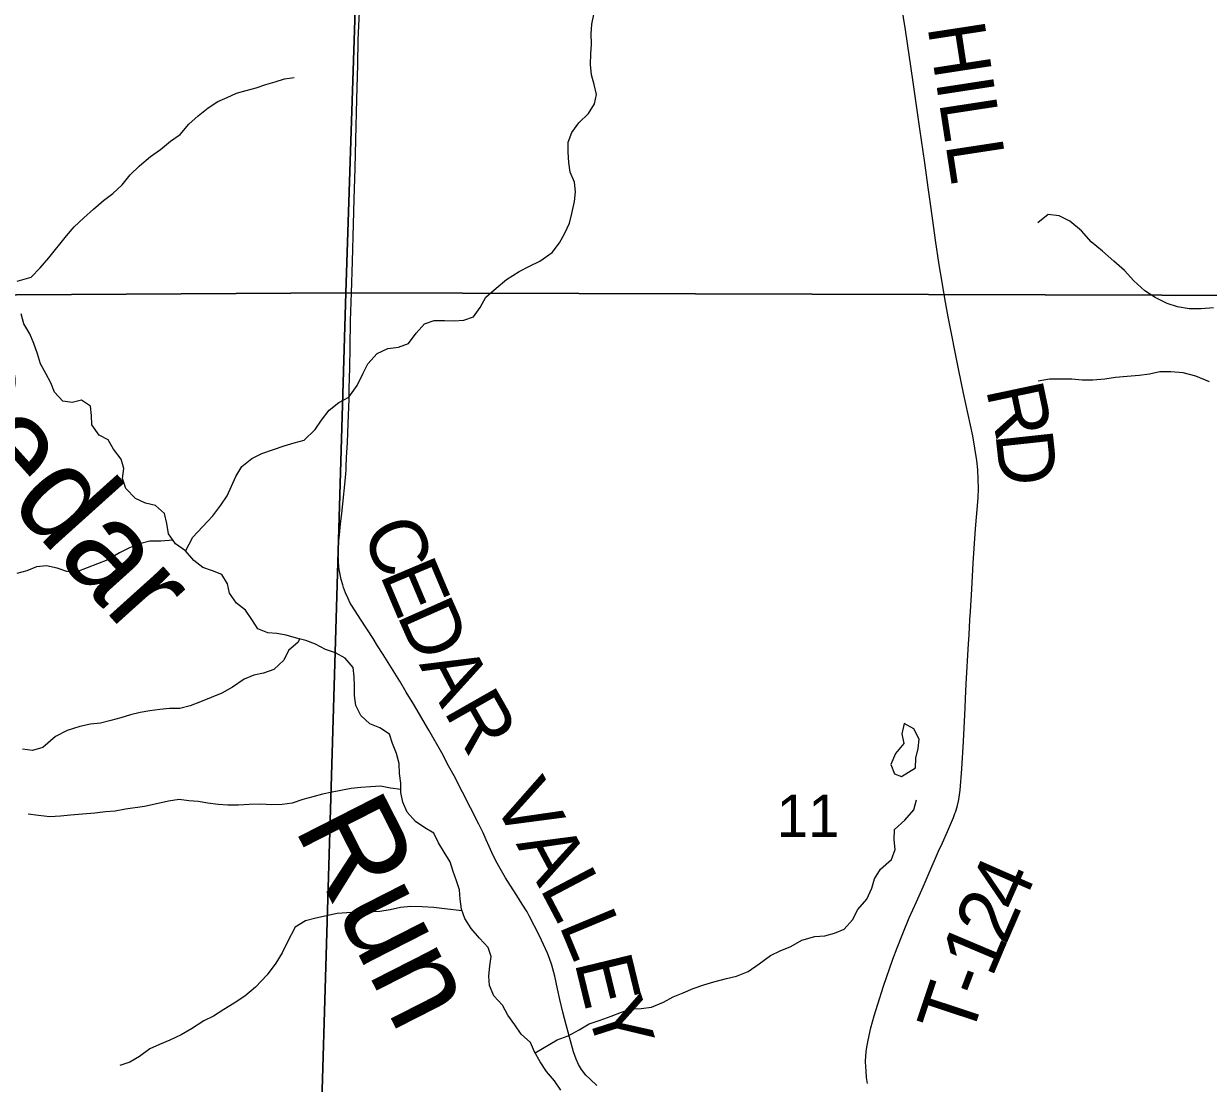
# Model space of a CAD drawing. Extents: x 1985906 to 2360102, y 891258 to 1222054.
# Drawn here: x 2095891 to 2102102, y 1047944 to 1053500 of the extents above; entities that cross this region are included whole.
import ezdxf

# ---------------------------------------------------------------- set-up
doc = ezdxf.new("R2010")
doc.units = 0
for name, color, linetype in [('GM_X_County_Road', 7, 'Continuous'), ('GM_X_County_Road_Text', 7, 'Continuous'), ('GM_X_Minor_Lake', 7, 'Continuous'), ('GM_X_Minor_River', 7, 'Continuous'), ('GM_X_Minor_River_Text', 7, 'Continuous'), ('GM_X_Section', 7, 'Continuous'), ('GM_X_Section_Text', 7, 'Continuous'), ('GM_X_Township_Road', 7, 'Continuous'), ('GM_X_Township_Road_Text', 7, 'Continuous')]:
    doc.layers.add(name, color=color, linetype=linetype)

msp = doc.modelspace()

# ---------------------------------------------------------------- linework, layer by layer
at = {"layer": 'GM_X_County_Road'}
msp.add_lwpolyline([(2098896.2, 1047932.2), (2098860, 1047965.5), (2098837.4, 1047987.2), (2098814.8, 1048015.9), (2098799.2, 1048042.8), (2098787, 1048069.7), (2098774.1, 1048109.6), (2098762.7, 1048147), (2098734.1, 1048250.3), (2098717.6, 1048316.3), (2098702, 1048382.3), (2098689.9, 1048439.6), (2098676, 1048504.8), (2098659.5, 1048563), (2098645.7, 1048603.5), (2098636.8, 1048626.7), (2098627.4, 1048648.9), (2098595.3, 1048716.7), (2098541.4, 1048821.3), (2098529.6, 1048842.5), (2098504.3, 1048882.6), (2098475.9, 1048927.7), (2098441.6, 1048983.4), (2098416.4, 1049021.5), (2098388.7, 1049069.3), (2098367, 1049110.9), (2098345.3, 1049154.7), (2098331.6, 1049185.2), (2098316.2, 1049219.7), (2098299.2, 1049257.6), (2098277.6, 1049302.9), (2098147.5, 1049555.2), (2098118.5, 1049608.9), (2098082.3, 1049676.3), (2098014.5, 1049796.1), (2097935.5, 1049930.7), (2097896.5, 1049994.1), (2097862.2, 1050051.5), (2097774.8, 1050192), (2097746, 1050238.3), (2097722.9, 1050275.5), (2097656.9, 1050377.1), (2097612.9, 1050445), (2097603.2, 1050462.2), (2097590, 1050489.1), (2097577.9, 1050516.1), (2097567.3, 1050542.9), (2097563.3, 1050556.9), (2097555.3, 1050584.7), (2097545.1, 1050638.7), (2097542.9, 1050650.8), (2097540.6, 1050681.9), (2097539.7, 1050718.4), (2097541.5, 1050772.2), (2097545.8, 1050820), (2097551.9, 1050877.3), (2097558.9, 1050931.1), (2097564, 1050981.5), (2097576.1, 1051100.4), (2097579.1, 1051138.7), (2097580.9, 1051161.3), (2097581.5, 1051177.1), (2097583.5, 1051224.7), (2097587.6, 1051304), (2097590.3, 1051352.3), (2097592, 1051403.5), (2097596.3, 1051532.9), (2097597.8, 1051586.7), (2097600.8, 1051695.4), (2097602.5, 1051803.8), (2097604.7, 1051940.9), (2097609.7, 1052088.2), (2097614, 1052252.1), (2097620.1, 1052448.6), (2097623.3, 1052579.6), (2097628, 1052743.1), (2097631.6, 1052890.5), (2097637.2, 1053103.4), (2097642, 1053283.6), (2097644.9, 1053414.8), (2097650.8, 1053561.8)], dxfattribs=at)
at = {"layer": 'GM_X_Minor_Lake'}
msp.add_line((2100457.3, 1049565.6), (2100493.3, 1049553), dxfattribs=at)
msp.add_lwpolyline([(2100493.3, 1049553), (2100566.2, 1049598.2), (2100569, 1049648.4), (2100579.7, 1049698.5), (2100586.5, 1049748.6), (2100557.1, 1049803.2), (2100507.3, 1049830), (2100494.5, 1049775.9), (2100505.8, 1049725.6), (2100460.9, 1049673.9), (2100438, 1049616), (2100457.3, 1049565.6)], dxfattribs=at)
at = {"layer": 'GM_X_Minor_River'}
for points in [[(2096739.7, 1050734.8), (2096777.9, 1050807.7), (2096828.9, 1050861.2), (2096881.9, 1050918.7), (2096924.9, 1050974.4), (2096957.8, 1051024.1), (2096980.6, 1051074), (2097003.4, 1051125.9), (2097034.3, 1051177.8), (2097087.1, 1051219.2), (2097139.7, 1051246.6), (2097200.2, 1051267.9), (2097256.7, 1051287.2), (2097309.2, 1051302.6), (2097361.6, 1051316), (2097418.6, 1051371.4), (2097451.5, 1051421.2), (2097492.4, 1051472.8), (2097543.2, 1051514.3), (2097595.8, 1051541.8), (2097638.8, 1051603.4), (2097669.9, 1051667.3), (2097694.7, 1051717.1), (2097743.7, 1051770.7), (2097800.3, 1051796.1), (2097856.6, 1051803.3), (2097909.1, 1051822.7), (2097948, 1051876.4), (2097992.9, 1051926), (2098043.4, 1051943.4), (2098097.6, 1051942.7), (2098147.8, 1051942), (2098198, 1051945.4), (2098248.5, 1051962.8), (2098283.3, 1052012.5), (2098314.2, 1052066.3), (2098367.1, 1052113.8), (2098422, 1052159.2), (2098488.9, 1052200.5), (2098543.5, 1052227.9), (2098596.1, 1052255.3), (2098661, 1052300.6), (2098699.9, 1052350.3), (2098728.8, 1052402.2), (2098751.6, 1052454.1), (2098764.4, 1052504.1), (2098779.3, 1052568.2), (2098784.1, 1052618.3), (2098778.8, 1052668.6), (2098755.4, 1052721.1), (2098748.1, 1052771.4), (2098744.9, 1052825.7), (2098745.6, 1052877.9), (2098764.5, 1052929.8), (2098801.3, 1052979.5), (2098852.2, 1053029.1), (2098883.1, 1053078.9), (2098893.8, 1053128.9), (2098882.5, 1053181.3), (2098867.2, 1053231.7), (2098861.9, 1053286), (2098864.8, 1053342.2), (2098867.5, 1053392.3), (2098866.3, 1053446.6), (2098869, 1053496.8), (2098879.8, 1053548.8)], [(2095856.5, 1052149.1), (2095929.9, 1052170.5), (2095976.8, 1052220.1), (2096021.7, 1052271.7), (2096115.8, 1052386.9), (2096154.6, 1052434.6), (2096205.5, 1052482.1), (2096256.3, 1052527.6), (2096309.2, 1052573.1), (2096357.9, 1052608.6), (2096406.8, 1052654.1), (2096449.7, 1052707.8), (2096498.6, 1052755.3), (2096555.5, 1052802.8), (2096608.3, 1052840.2), (2096661.1, 1052883.7), (2096711.8, 1052919.1), (2096756.8, 1052972.8), (2096805.6, 1053016.3), (2096858.4, 1053057.8), (2096909.1, 1053091.2), (2096957.6, 1053112.7), (2097006.1, 1053136.1), (2097056.5, 1053149.5), (2097108.9, 1053162.8), (2097159.4, 1053180.2), (2097209.8, 1053195.6), (2097258.2, 1053211.1), (2097308.6, 1053218.4)], [(2102129.2, 1052009.2), (2102064.8, 1052004), (2102000.6, 1052004.9), (2101940.5, 1052015.8), (2101886.5, 1052032.5), (2101822.7, 1052063.5), (2101768.9, 1052098.4), (2101711.5, 1052151.4), (2101662.1, 1052206.2), (2101606.5, 1052255.2), (2101547, 1052306.2), (2101487.5, 1052355.2), (2101436.1, 1052414.1), (2101376.6, 1052465.1), (2101320.7, 1052492), (2101262.6, 1052498.8), (2101207.7, 1052455.3)], [(2095979.6, 1051716), (2095962.3, 1051768.4), (2095943, 1051822.9), (2095923.6, 1051873.4), (2095892.2, 1051926), (2095876.9, 1051978.4)], [(2098706.4, 1047908.1), (2098673, 1047956.8), (2098631.5, 1048005.5), (2098598.1, 1048056.2), (2098568.7, 1048108.8), (2098547.3, 1048157.3), (2098499.8, 1048202.1), (2098466.3, 1048250.7), (2098428.9, 1048301.4), (2098401.5, 1048354), (2098356, 1048402.8), (2098332.7, 1048457.4), (2098329.4, 1048505.6), (2098334.2, 1048559.8), (2098340.9, 1048607.9), (2098325.5, 1048656.3), (2098280.1, 1048705.1), (2098236.6, 1048755.9), (2098203.2, 1048808.5), (2098185.8, 1048856.9), (2098178.6, 1048909.3), (2098175.2, 1048957.5), (2098159.9, 1049005.9), (2098142.5, 1049054.3), (2098127.1, 1049104.7), (2098095.7, 1049155.4), (2098066.3, 1049204), (2098040.9, 1049254.5), (2097993.1, 1049283.3), (2097945.4, 1049316), (2097901.9, 1049364.8), (2097878.6, 1049417.3), (2097867.3, 1049467.7), (2097868, 1049517.9), (2097860.7, 1049568.2), (2097859.4, 1049620.4), (2097846.1, 1049672.8), (2097824.8, 1049725.3), (2097809.4, 1049773.7), (2097757.7, 1049808.5), (2097705.8, 1049829.3), (2097658.2, 1049872.1), (2097632.8, 1049924.7), (2097625.5, 1049977), (2097624.3, 1050027.2), (2097622.9, 1050075.4), (2097617.6, 1050123.7), (2097576.1, 1050172.4), (2097526.3, 1050201.2), (2097472.4, 1050218), (2097420.6, 1050246.8), (2097370.6, 1050265.6), (2097320.6, 1050278.3), (2097266.6, 1050293.1), (2097218.5, 1050301.7), (2097170.4, 1050306.4), (2097118.5, 1050327.2), (2097087, 1050375.8), (2097053.6, 1050424.4), (2097005.9, 1050461.2), (2096970.5, 1050513.9), (2096959.2, 1050562.2), (2096929.7, 1050610.8), (2096879.8, 1050631.6), (2096829.9, 1050648.3), (2096782.2, 1050685.1), (2096738.7, 1050735.9), (2096687, 1050772.7), (2096649.6, 1050825.4), (2096640.4, 1050879.8), (2096629.1, 1050932.2), (2096581.5, 1050972.9), (2096529.4, 1050985.7), (2096477.6, 1051010.5), (2096426.1, 1051063.4), (2096408.8, 1051115.8), (2096415.6, 1051168), (2096402.2, 1051216.3), (2096360.8, 1051269.1), (2096333.4, 1051317.7), (2096285.5, 1051342.4), (2096248.2, 1051397.1), (2096246.8, 1051445.3), (2096241.5, 1051493.6), (2096193.8, 1051526.4), (2096145.4, 1051513), (2096095.3, 1051519.7), (2096051.8, 1051568.4), (2096032.4, 1051616.9), (2096007, 1051665.4), (2095979.6, 1051716)], [(2102107.5, 1051621.9), (2102035.6, 1051651), (2101969.6, 1051669.9), (2101905.4, 1051674.8), (2101847.2, 1051673.6), (2101792.8, 1051662.3), (2101738.5, 1051655), (2101676.1, 1051649.8), (2101615.8, 1051644.6), (2101559.5, 1051635.3), (2101497.1, 1051630.1), (2101440.9, 1051630.8), (2101386.7, 1051635.6), (2101322.5, 1051636.4), (2101268.3, 1051635.2), (2101209.9, 1051625.9)], [(2096673.9, 1050791.3), (2096608.9, 1050785.8), (2096552.7, 1050786.6), (2096498.3, 1050773.2), (2096445.8, 1050751.9), (2096393.1, 1050724.4), (2096332.4, 1050689.1), (2096168.8, 1050625), (2096116.6, 1050627.7), (2096066.6, 1050644.5), (2096010.6, 1050657.3), (2095958.3, 1050651.9), (2095907.8, 1050630.5), (2095855.4, 1050617.2)], [(2097337.5, 1050274), (2097330.3, 1050256.1), (2097279.5, 1050212.6), (2097254.7, 1050162.7), (2097201.7, 1050113.2), (2097147.2, 1050093.8), (2097096.9, 1050084.5), (2097046.4, 1050063.1), (2096985.5, 1050021.7), (2096928.9, 1049990.3), (2096874.3, 1049967), (2096817.7, 1049943.6), (2096763.2, 1049922.3), (2096708.8, 1049908.9), (2096654.6, 1049909.6), (2096604.3, 1049904.3), (2096552, 1049897), (2096501.6, 1049887.6), (2096451.3, 1049876.2), (2096400.8, 1049860.8), (2096348.4, 1049845.5), (2096294, 1049832.1), (2096241.7, 1049826.8), (2096185.3, 1049815.5), (2096118.7, 1049794.3), (2096058, 1049763), (2095990.9, 1049703.7), (2095936.4, 1049688.3), (2095884.3, 1049695)], [(2097867.5, 1049483.8), (2097813.4, 1049490.5), (2097761.3, 1049501.2), (2097709, 1049497.9), (2097658.8, 1049494.6), (2097608.5, 1049489.2), (2097507.8, 1049470.5), (2097457.4, 1049459.1), (2097407, 1049445.7), (2097354.6, 1049432.4), (2097298.1, 1049413.1), (2097245.8, 1049405.7), (2097191.6, 1049404.4), (2097131.4, 1049407.2), (2097073.1, 1049406), (2097016.8, 1049402.8), (2096960.6, 1049401.5), (2096910.4, 1049406.2), (2096856.3, 1049412.9), (2096806.2, 1049421.6), (2096756.1, 1049424.3), (2096706, 1049431), (2096649.6, 1049423.7), (2096595.2, 1049410.4), (2096524.7, 1049395.3), (2096424.1, 1049380.6), (2096369.7, 1049371.2), (2096319.5, 1049367.9), (2096263.1, 1049360.6), (2096198.8, 1049355.5), (2096136.4, 1049350.3), (2096084.2, 1049344.9), (2096027.9, 1049341.7), (2095967.7, 1049348.5), (2095913.6, 1049355.3)], [(2098571.9, 1048103.1), (2098688.1, 1048171.5), (2098744.6, 1048192.8), (2098803.3, 1048224.1), (2098856, 1048255.6), (2098912.5, 1048274.9), (2098971.1, 1048296.2), (2099025.6, 1048317.6), (2099078.1, 1048334.9), (2099128.3, 1048336.3), (2099182.6, 1048343.6), (2099245.2, 1048368.8), (2099295.8, 1048396.3), (2099348.3, 1048417.7), (2099400.9, 1048441.1), (2099457.4, 1048460.4), (2099509.8, 1048475.8), (2099576.4, 1048492.9), (2099628.8, 1048506.3), (2099689.3, 1048529.6), (2099746.2, 1048571), (2099807, 1048614.3), (2099857.6, 1048637.8), (2099912.1, 1048661.1), (2099970.9, 1048694.5), (2100039.4, 1048713.6), (2100091.7, 1048717), (2100142.1, 1048730.4), (2100192.6, 1048751.8), (2100235.5, 1048801.4), (2100264.4, 1048855.2), (2100311.3, 1048908.8), (2100338.3, 1048966.7), (2100351, 1049016.7), (2100383.9, 1049066.5), (2100440.9, 1049117.9), (2100459.7, 1049169.9), (2100454.4, 1049220.2), (2100457.2, 1049274.4), (2100510.1, 1049323.9), (2100557, 1049377.4), (2100571.9, 1049429.5)], [(2098189.2, 1048847.4), (2098097.5, 1048858.1), (2098041.4, 1048864.9), (2097979.2, 1048869.8), (2097920.9, 1048870.5), (2097866.6, 1048865.2), (2097812.3, 1048853.9), (2097757.9, 1048844.6), (2097693.6, 1048841.4), (2097639.3, 1048840.2), (2097585.1, 1048836.9), (2097534.8, 1048833.5), (2097478.4, 1048822.2), (2097422, 1048808.9), (2097367.6, 1048795.6), (2097314.9, 1048762.2), (2097273.6, 1048686.4), (2097246.7, 1048628.5), (2097211.8, 1048572.8), (2097166.7, 1048513.1), (2097105.5, 1048447.7), (2097050.6, 1048400.2), (2096993.9, 1048364.8), (2096939.2, 1048331.4), (2096886.5, 1048296), (2096835.9, 1048270.6), (2096771, 1048229.3), (2096716.4, 1048197.9), (2096657.7, 1048170.5), (2096603.2, 1048147.2), (2096552.6, 1048123.7), (2096497.8, 1048084.3), (2096447.2, 1048054.9), (2096394.7, 1048037.5)]]:
    msp.add_lwpolyline(points, dxfattribs=at)
at = {"layer": 'GM_X_Section'}
for points in [[(2097994, 1057075.2), (2103253.1, 1057114.6), (2103079.3, 1052072.7), (2097579.8, 1052088.1), (2097743.8, 1057069.9)], [(2092680.8, 1057037.4), (2097743.8, 1057069.9), (2097579.8, 1052088.1), (2092108.6, 1052055.6), (2092232.6, 1057031.2)], [(2092108.6, 1052055.6), (2097579.8, 1052088.1), (2097447.4, 1047614.8), (2097492.7, 1047615), (2097478.9, 1046742.4), (2091937.8, 1046691.4)], [(2097579.8, 1052088.1), (2103079.3, 1052072.7), (2102958.6, 1047645.4), (2102999.9, 1047645.6), (2102970.3, 1046741.1), (2097478.9, 1046742.4), (2097492.7, 1047615), (2097447.4, 1047614.8)]]:
    msp.add_lwpolyline(points, close=True, dxfattribs=at)
at = {"layer": 'GM_X_Township_Road'}
msp.add_lwpolyline([(2100314.4, 1047942.6), (2100310.4, 1047974.8), (2100307.3, 1048007.5), (2100305.2, 1048056.7), (2100306.3, 1048089.4), (2100309.9, 1048122), (2100318.1, 1048170.5), (2100332.5, 1048234.5), (2100350.2, 1048297.6), (2100369, 1048358.6), (2100399.4, 1048453.3), (2100447.2, 1048593.9), (2100469.9, 1048654.4), (2100499.3, 1048729.4), (2100534.1, 1048811.9), (2100571.4, 1048896.1), (2100606.2, 1048973.4), (2100638.3, 1049048.1), (2100687.7, 1049160.7), (2100707.3, 1049205.1), (2100733.7, 1049263.7), (2100765.5, 1049338.1), (2100772.9, 1049358), (2100775.5, 1049365.6), (2100779.1, 1049376.2), (2100786.3, 1049400.2), (2100791.5, 1049423.1), (2100792.9, 1049431.3), (2100795.1, 1049444.1), (2100800.1, 1049480.4), (2100810.1, 1049593.3), (2100818.8, 1049736.1), (2100825.8, 1049877.9), (2100827.2, 1049911.2), (2100829.4, 1049961.5), (2100830.9, 1049998), (2100832.7, 1050038.5), (2100844.8, 1050247.5), (2100847.4, 1050296), (2100852.2, 1050373.9), (2100854.8, 1050417.4), (2100861.7, 1050534.6), (2100869.6, 1050671.8), (2100881.8, 1050850.7), (2100895, 1051014), (2100896.1, 1051063.2), (2100895.6, 1051112.2), (2100893, 1051161), (2100888.1, 1051209.6), (2100878.4, 1051274.1), (2100866.4, 1051338.3), (2100818.2, 1051561.9), (2100791.5, 1051689.9), (2100737.8, 1051962.1), (2100720.6, 1052058.5), (2100704.4, 1052155), (2100691.4, 1052235.4), (2100671.6, 1052364.5), (2100662.5, 1052429.5), (2100647.4, 1052543), (2100633.6, 1052640.3), (2100614.7, 1052770.2), (2100589.8, 1052948.9), (2100554.4, 1053192.5), (2100513.3, 1053468.3), (2100482.2, 1053662.7)], dxfattribs=at)

# ---------------------------------------------------------------- texts
at = {"layer": 'GM_X_County_Road_Text'}
for s, rotation, p in [('C', 292.90929, (2097659.7, 1050838.8)), ('E', 292.91279, (2097755.6, 1050611.8)), ('D', 293.93756, (2097845.3, 1050399.7)), ('A', 297.60001, (2097961.5, 1050139.6)), ('R', 299.61806, (2098089.4, 1049895.5)), ('V', 298.06724, (2098345.6, 1049432.1)), ('A', 298.0591, (2098469.9, 1049199.2)), ('L', 297.75725, (2098593.8, 1048966.6)), ('L', 292.59647, (2098695.3, 1048774.5)), ('E', 283.63918, (2098777.7, 1048579.1)), ('Y', 287.71821, (2098836.9, 1048338.5))]:
    msp.add_text(s, height=300, rotation=rotation, dxfattribs=at).set_placement(p)
at = {"layer": 'GM_X_Minor_River_Text'}
for s, height, rotation, p in [('Cedar', 500.18, 311.98753, (2095237.8, 1051618.9)), ('Run', 500.19, 296.98824, (2097305.3, 1049285.5))]:
    msp.add_text(s, height=height, rotation=rotation, dxfattribs=at).set_placement(p)
at = {"layer": 'GM_X_Section_Text'}
msp.add_text('11', height=221, rotation=0.00001, dxfattribs=at).set_placement((2099839, 1049235.6))
at = {"layer": 'GM_X_Township_Road_Text'}
for s, rotation, p in [('HILL', 278.72265, (2100628.8, 1053485.8)), ('R', 281.94183, (2100935.2, 1051584.4)), ('D', 276.16984, (2100985, 1051351.2)), ('4', 66.25202, (2101111.6, 1048831.3)), ('2', 66.6251, (2101038.5, 1048662.1)), ('1', 67.12872, (2100966.9, 1048492.5)), ('-', 69.23289, (2100924.3, 1048380)), ('T', 71.66804, (2100854.9, 1048170.2))]:
    msp.add_text(s, height=300, rotation=rotation, dxfattribs=at).set_placement(p)

doc.saveas('drawing.dxf')
